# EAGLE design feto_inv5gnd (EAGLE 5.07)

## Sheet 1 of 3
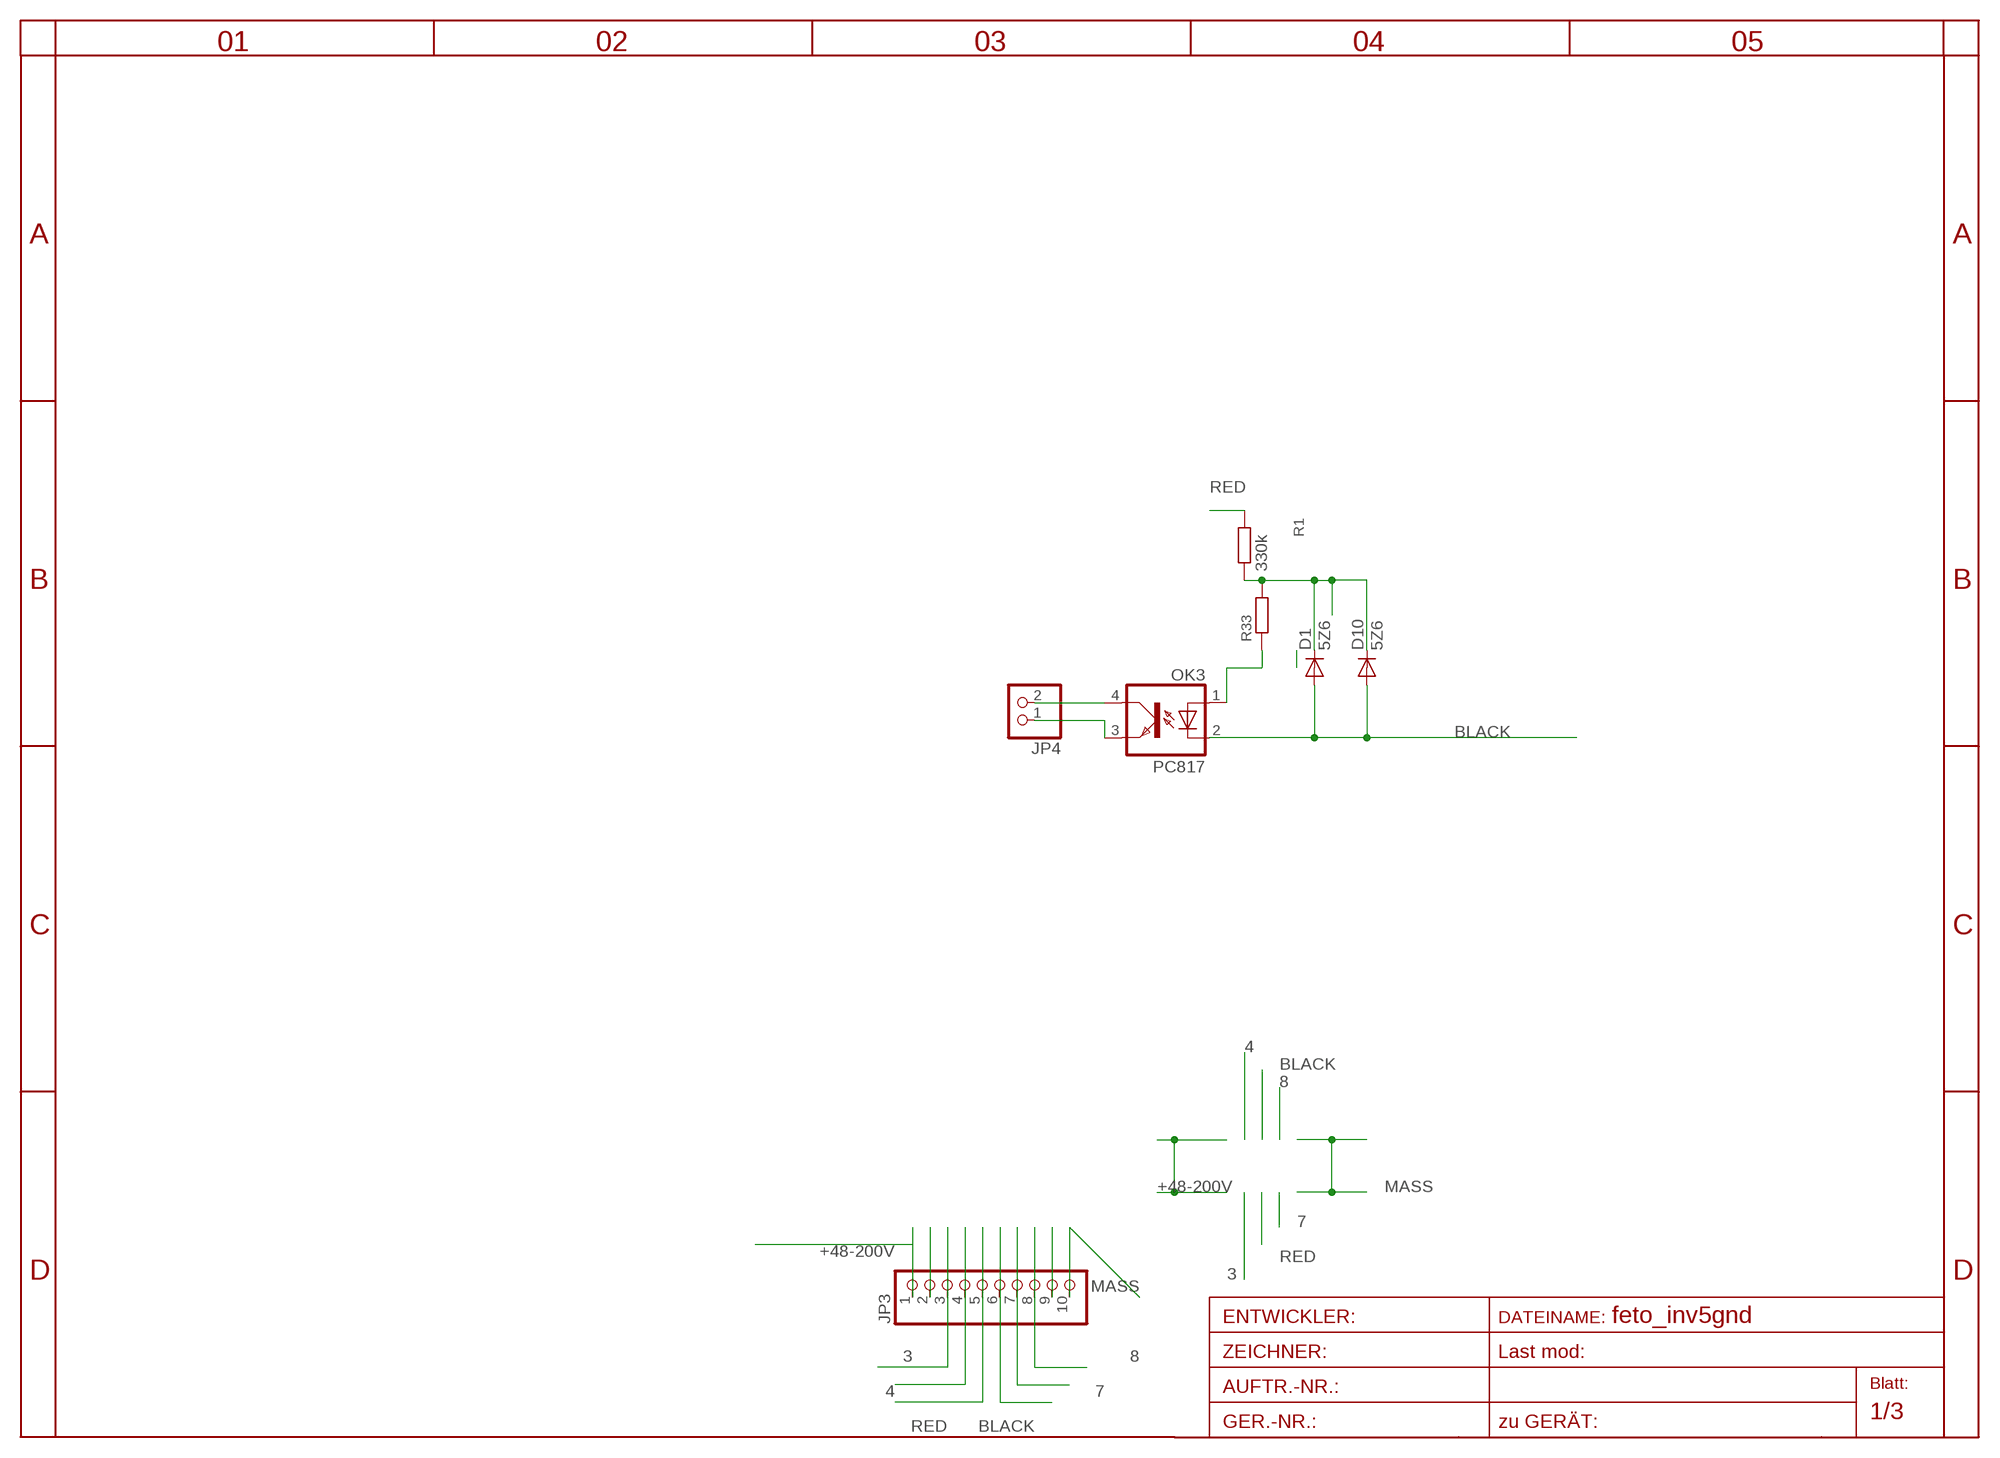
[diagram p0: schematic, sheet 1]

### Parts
D1  5Z6  DIODE-MINIMELF  [MINIMELF]
D10  5Z6  DIODE-MINIMELF  [MINIMELF]
JP3  PINHD-1X10  [1X10WIDE]
JP4  PINHD-1X2STR  [1X02]
OK3  PC817  [DIL04]
R1  330k  R-EU_0204/5  [0204/5]
R33  4k  R-EU_R0805  [R0805]

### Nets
3: JP3.3 ; also sheet 3
4: JP3.4 ; also sheet 3
7: JP3.7 ; also sheet 3
8: JP3.8 ; also sheet 3
+48-200V: JP3.1
BLACK: D1.A D10.A JP3.6 OK3.2(C) ; also sheet 3
MASS: JP3.10 ; also sheet 3
N$3: JP4.2 OK3.4(COL)
N$4: JP4.1 OK3.3(EMIT)
N$25: JP3.2
N$34: JP3.9
N$35: OK3.1(A) R33.1
N$36: D1.C D10.C R1.1 R33.2
RED: JP3.5 R1.2 ; also sheet 3

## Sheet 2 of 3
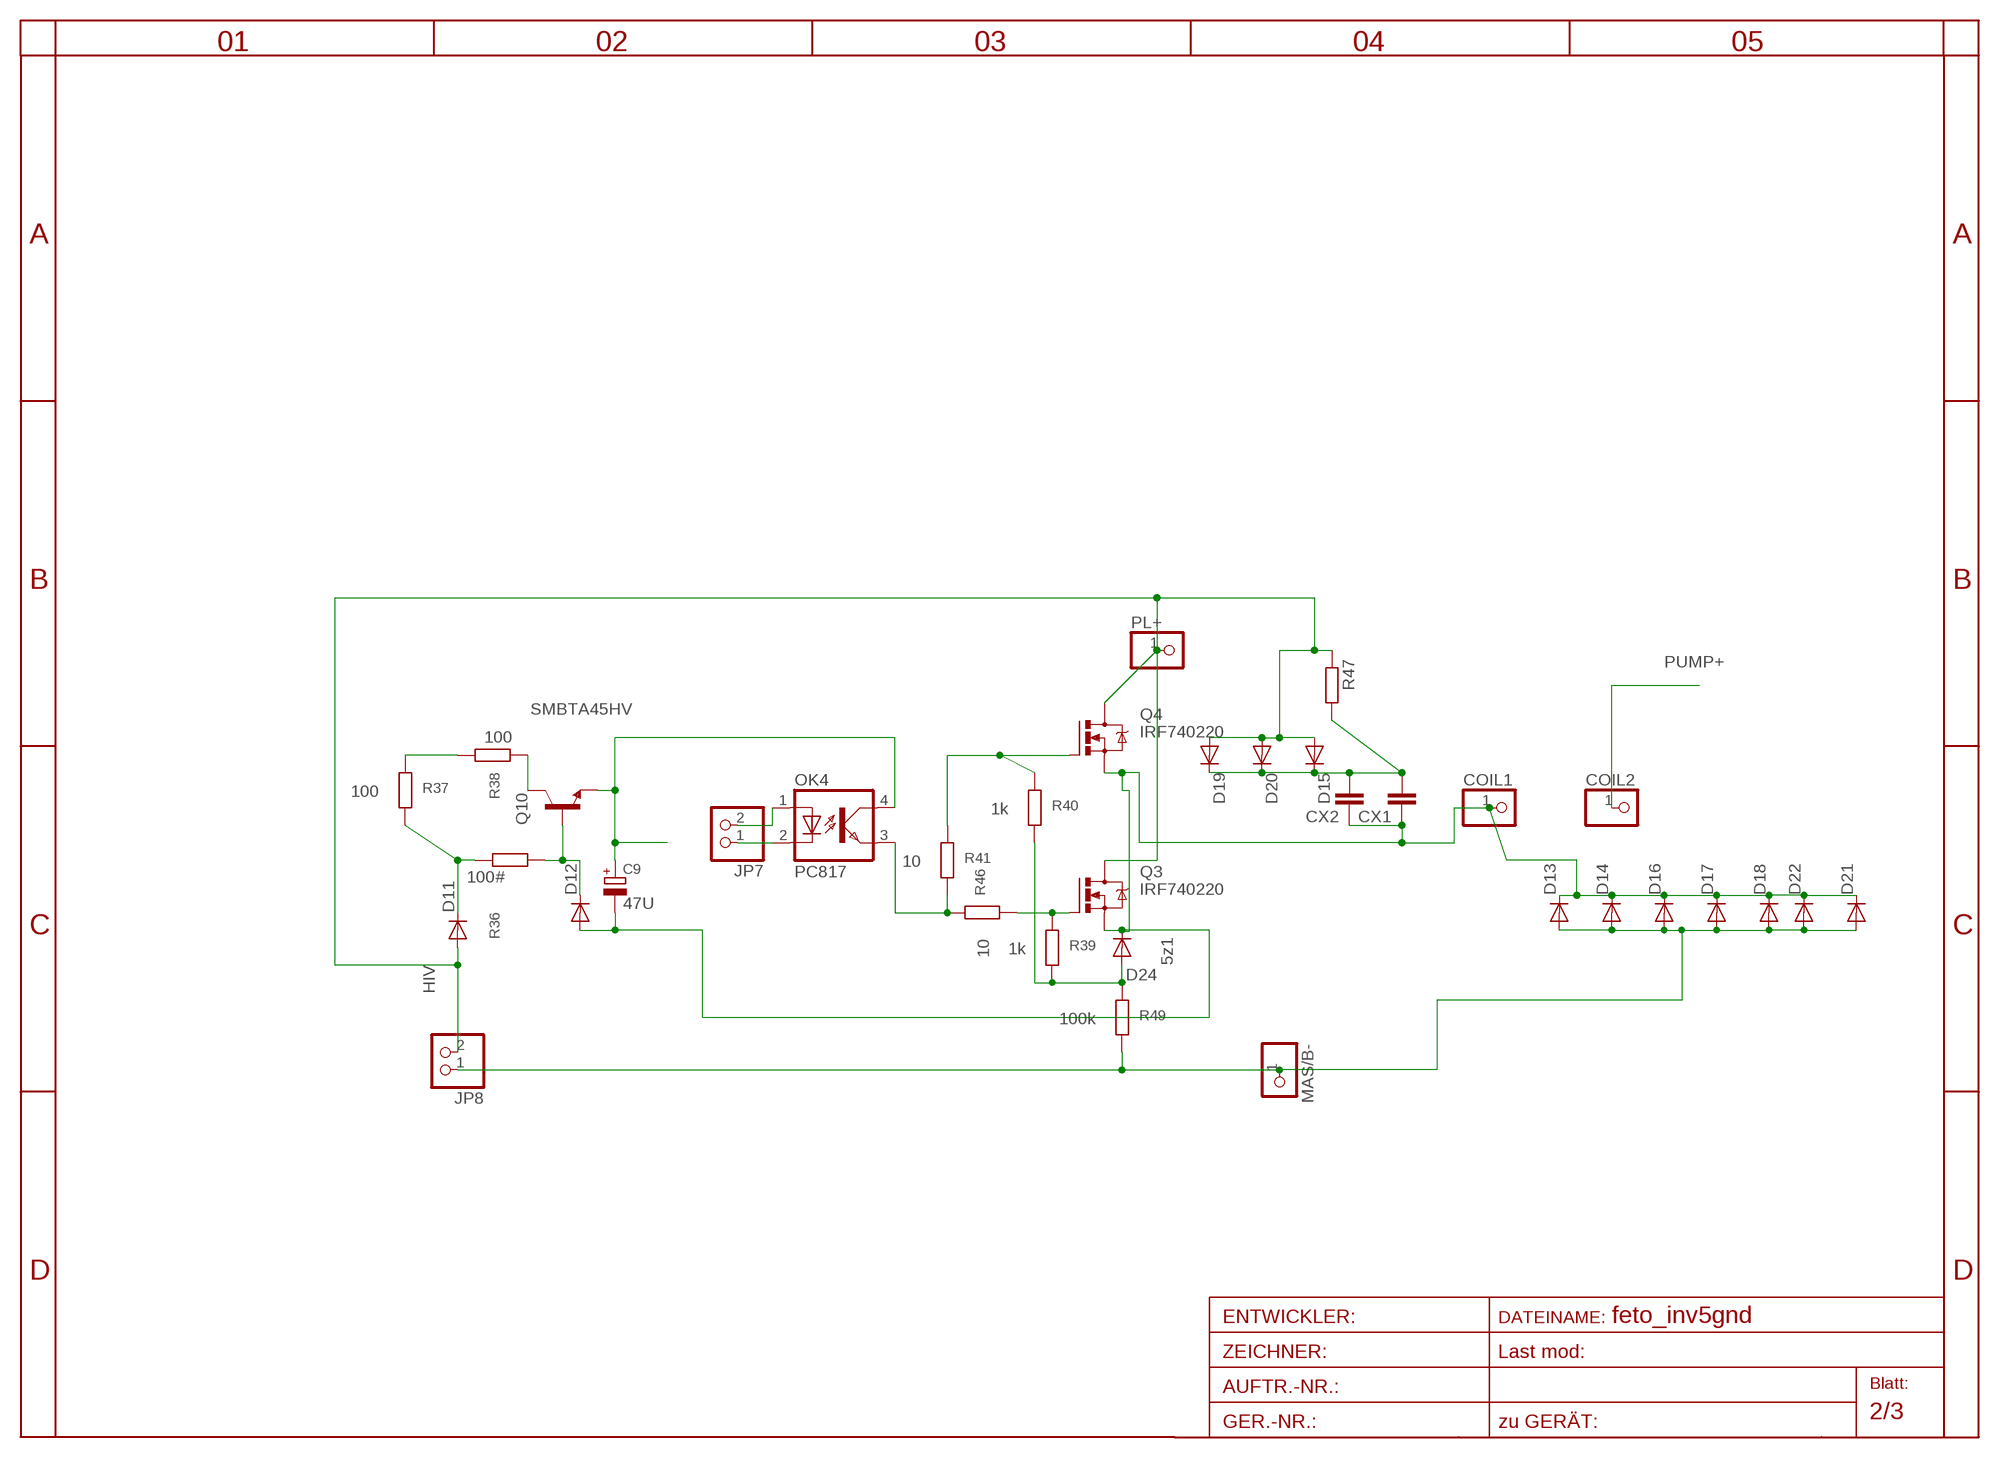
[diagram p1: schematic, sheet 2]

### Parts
C9  47U  CPOL-EUE2.5-6  [E2,5-6]
COIL1  PINHD-1X14.5MM  [1X4MM5]
COIL2  PINHD-1X14.5MM  [1X4MM5]
CX1  CXXC15B6  [XC15B6]
CX2  CXXC15B6  [XC15B6]
D11  DIODE-SMA-DO214  [SMA-DO214AC]
D12  DIODE-MINIMELF  [MINIMELF]
D13  DIODE-SMC  [SMC]
D14  DIODE-SMC  [SMC]
D15  DIODE-SMC  [SMC]
D16  DIODE-SMC  [SMC]
D17  DIODE-SMC  [SMC]
D18  DIODE-SMC  [SMC]
D19  DIODE-SMC  [SMC]
D20  DIODE-SMC  [SMC]
D21  DIODE-SMC  [SMC]
D22  DIODE-SMC  [SMC]
D24  5z1  DIODE-MINIMELF  [MINIMELF]
JP7  PINHD-1X2STR  [1X02]
JP8  PINHD-1X2STR  [1X02]
MAS/B-  PINHD-1X14.5MM  [1X4MM5]
OK4  PC817  [DIL04]
PL+  PINHD-1X14.5MM  [1X4MM5]
Q3  IRF740220  [TO220BV]
Q4  IRF740220  [TO220BV]
Q10  SMBTA45HV  [SOT23HV]
R36  100#  R-EU_R1206  [R1206]
R37  100  R-EU_R1206  [R1206]
R38  100  R-EU_R1206  [R1206]
R39  1k  R-EU_0207/30  [0207/30]
R40  1k  R-EU_0207/15  [0207/15]
R41  10  R-EU_0207/12  [0207/12]
R46  10  R-EU_0207/25  [0207/25]
R47  R-EU_CERAM35  [CERAM35]
R49  100k  R-EU_R1206  [R1206]

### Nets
B-: D13.A D14.A D16.A D17.A D18.A D21.A D22.A JP8.1 MAS/B-.1 R49.1
BATT-: D24.A R39.1 R40.1 R49.2
COIL1: C9.- COIL1.1 CX1.1 CX2.1 D12.A D13.C D14.C D16.C D17.C D18.C D21.C D22.C D24.C Q3.S Q4.S
HIV: D11.A D15.A D19.A D20.A JP8.2 PL+.1 Q3.D Q4.D R47.1
N$1: Q4.G R40.2 R41.2
N$42: JP7.1 OK4.2(C)
N$43: OK4.3(EMIT) R41.1 R46.2
N$44: JP7.2 OK4.1(A)
N$45: Q3.G R39.2 R46.1
N$48: C9.+ OK4.4(COL) Q10.2(E)
N$49: D11.K(C) R36.1 R37.1
N$50: R37.2 R38.1
N$51: D12.C Q10.1(B) R36.2
PUMP+: COIL2.1 ; also sheet 3
Q1: Q10.3(C) R38.2
SNUB: CX1.2 CX2.2 D15.C D19.C D20.C R47.2

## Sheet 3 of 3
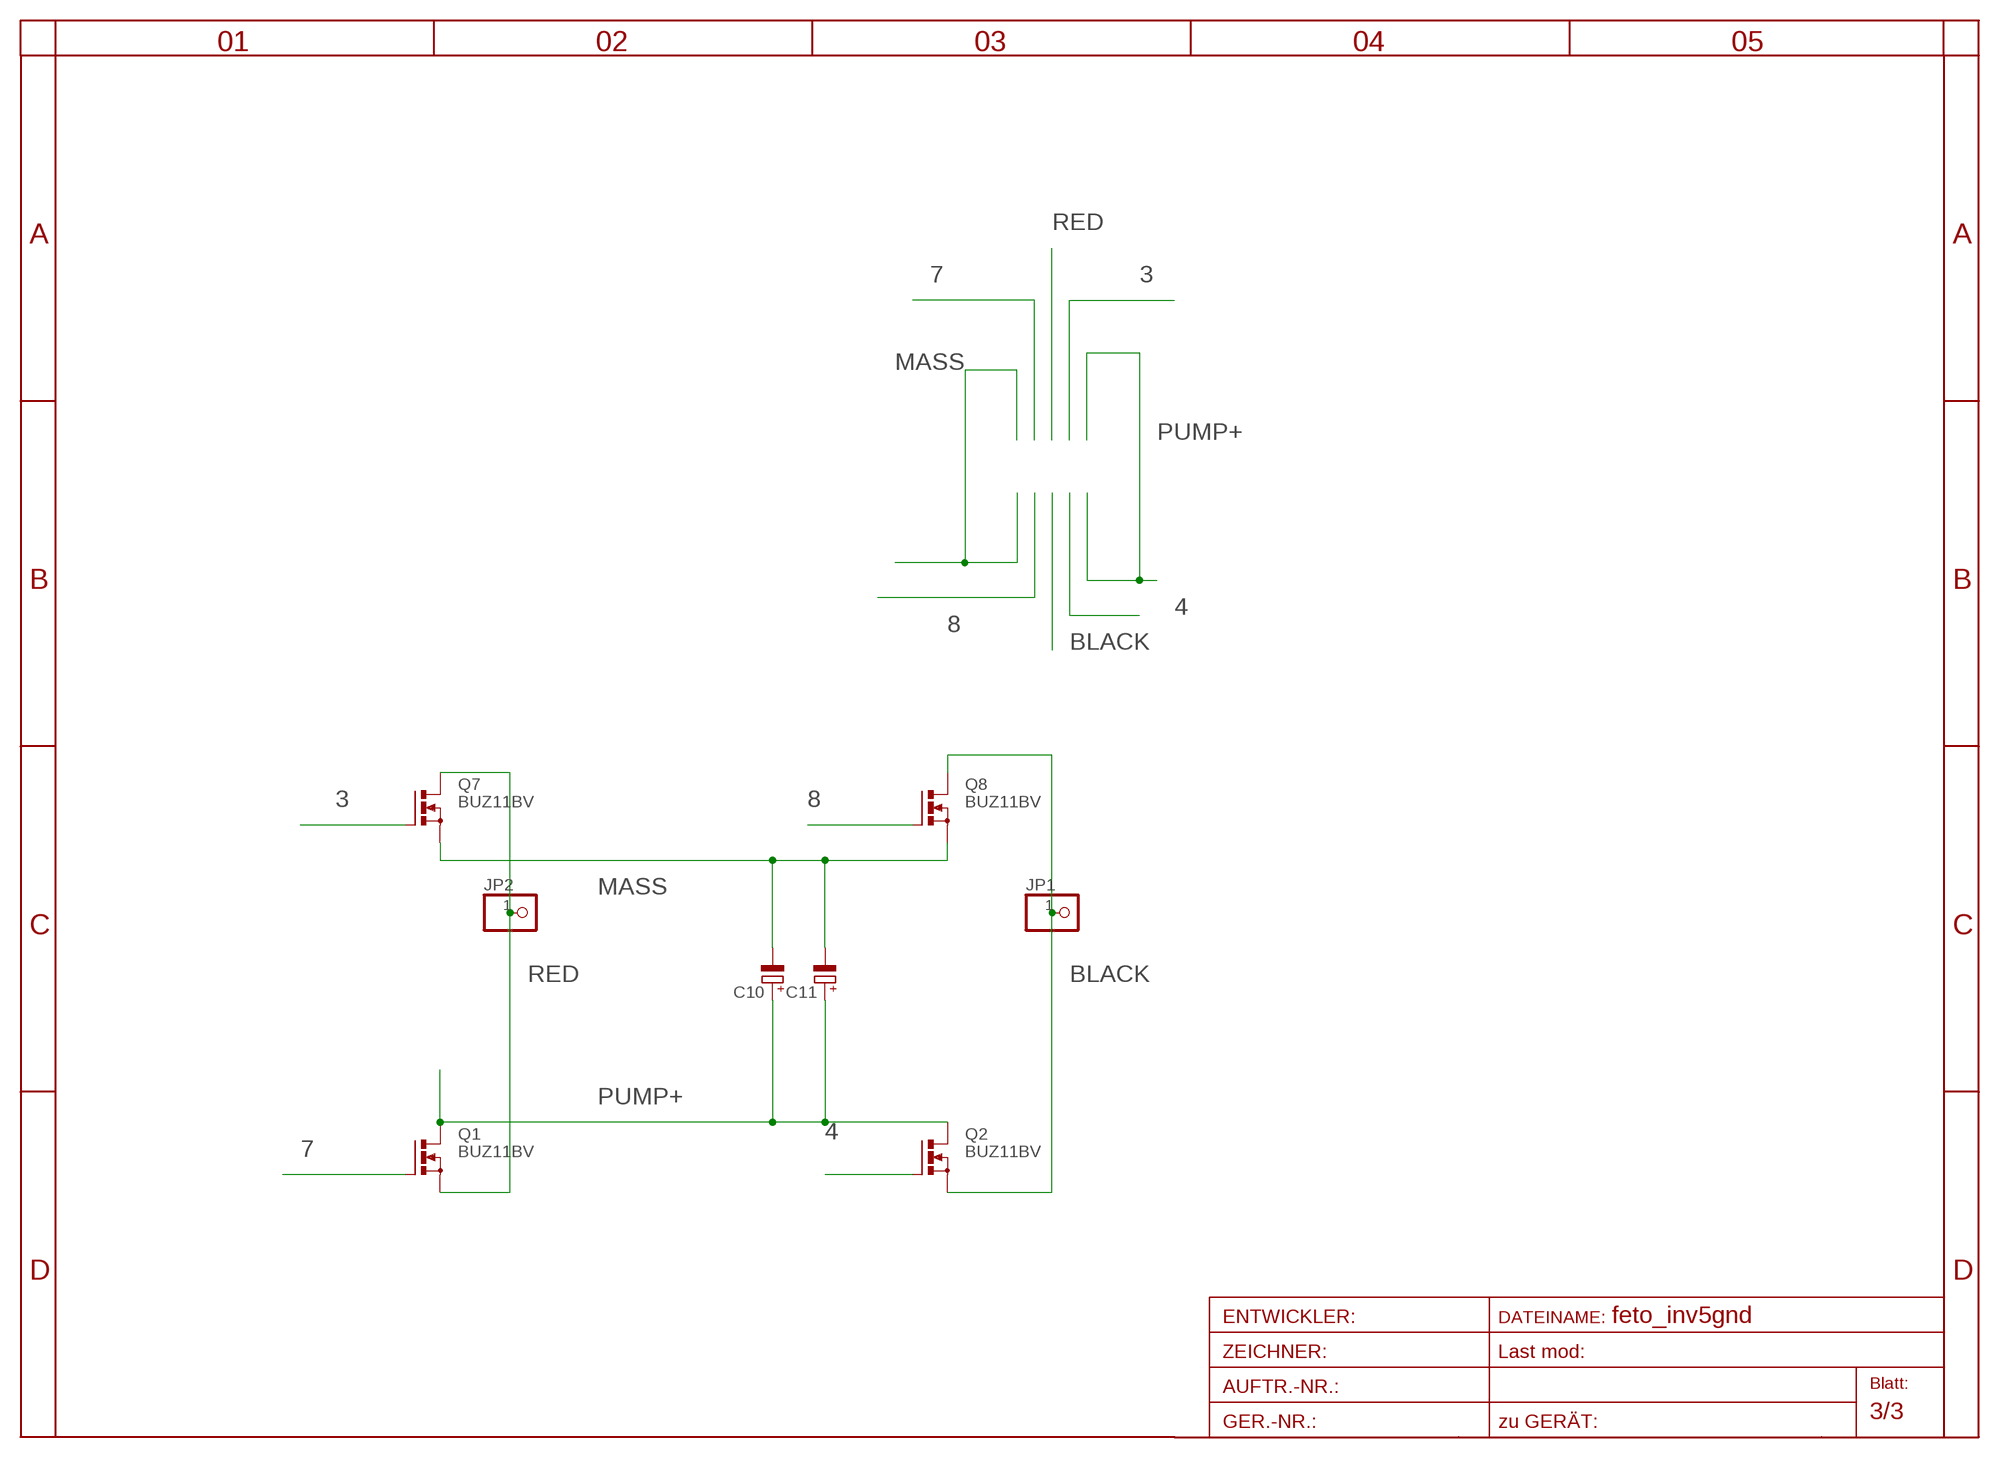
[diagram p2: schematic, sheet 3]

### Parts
C10  CPOL-EUE7.5-18  [E7,5-18]
C11  CPOL-EUE7.5-18  [E7,5-18]
JP1  PINHD-1X13MM2  [1X3MM2]
JP2  PINHD-1X13MM2  [1X3MM2]
Q1  BUZ11BV  [TO220BV]
Q2  BUZ11BV  [TO220BV]
Q7  BUZ11BV  [TO220BV]
Q8  BUZ11BV  [TO220BV]

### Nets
3: Q7.G ; also sheet 1
4: Q2.G ; also sheet 1
7: Q1.G ; also sheet 1
8: Q8.G ; also sheet 1
BLACK: JP1.1 Q2.S Q8.D ; also sheet 1
MASS: C10.- C11.- Q7.S Q8.S ; also sheet 1
PUMP+: C10.+ C11.+ Q1.D Q2.D ; also sheet 2
RED: JP2.1 Q1.S Q7.D ; also sheet 1

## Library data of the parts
C9 = rcl-2:CPOL-EU: POLARIZED CAPACITOR, European symbol
C10 C11 = rcl:CPOL-EU: POLARIZED CAPACITOR, European symbol
COIL1 COIL2 JP1 JP2 MAS/B- PL+ = pinhead:PINHD-1X1: PIN HEADER
CX1 CX2 = rcl:CX: X CAPACITOR
D1 D10-D22 D24 = diode:DIODE-: DIODE
JP3 = pinhead:PINHD-1X10: PIN HEADER
JP4 JP7 JP8 = pinhead:PINHD-1X2: PIN HEADER
OK3 OK4 = optocoupler:PC817: SHARP OPTO COUPLER
Q1 Q2 Q7 Q8 = transistor-power:BUZ11: N-CHANNEL MOS FET
Q3 Q4 = transistor-power:IRF740: N-CHANNEL MOS FET
Q10 = transistor-npn:SMBTA45
R1 R33 R36-R41 R46 R49 = rcl-2:R-EU_: RESISTOR, European symbol
R47 = rcl:R-EU_: RESISTOR, European symbol

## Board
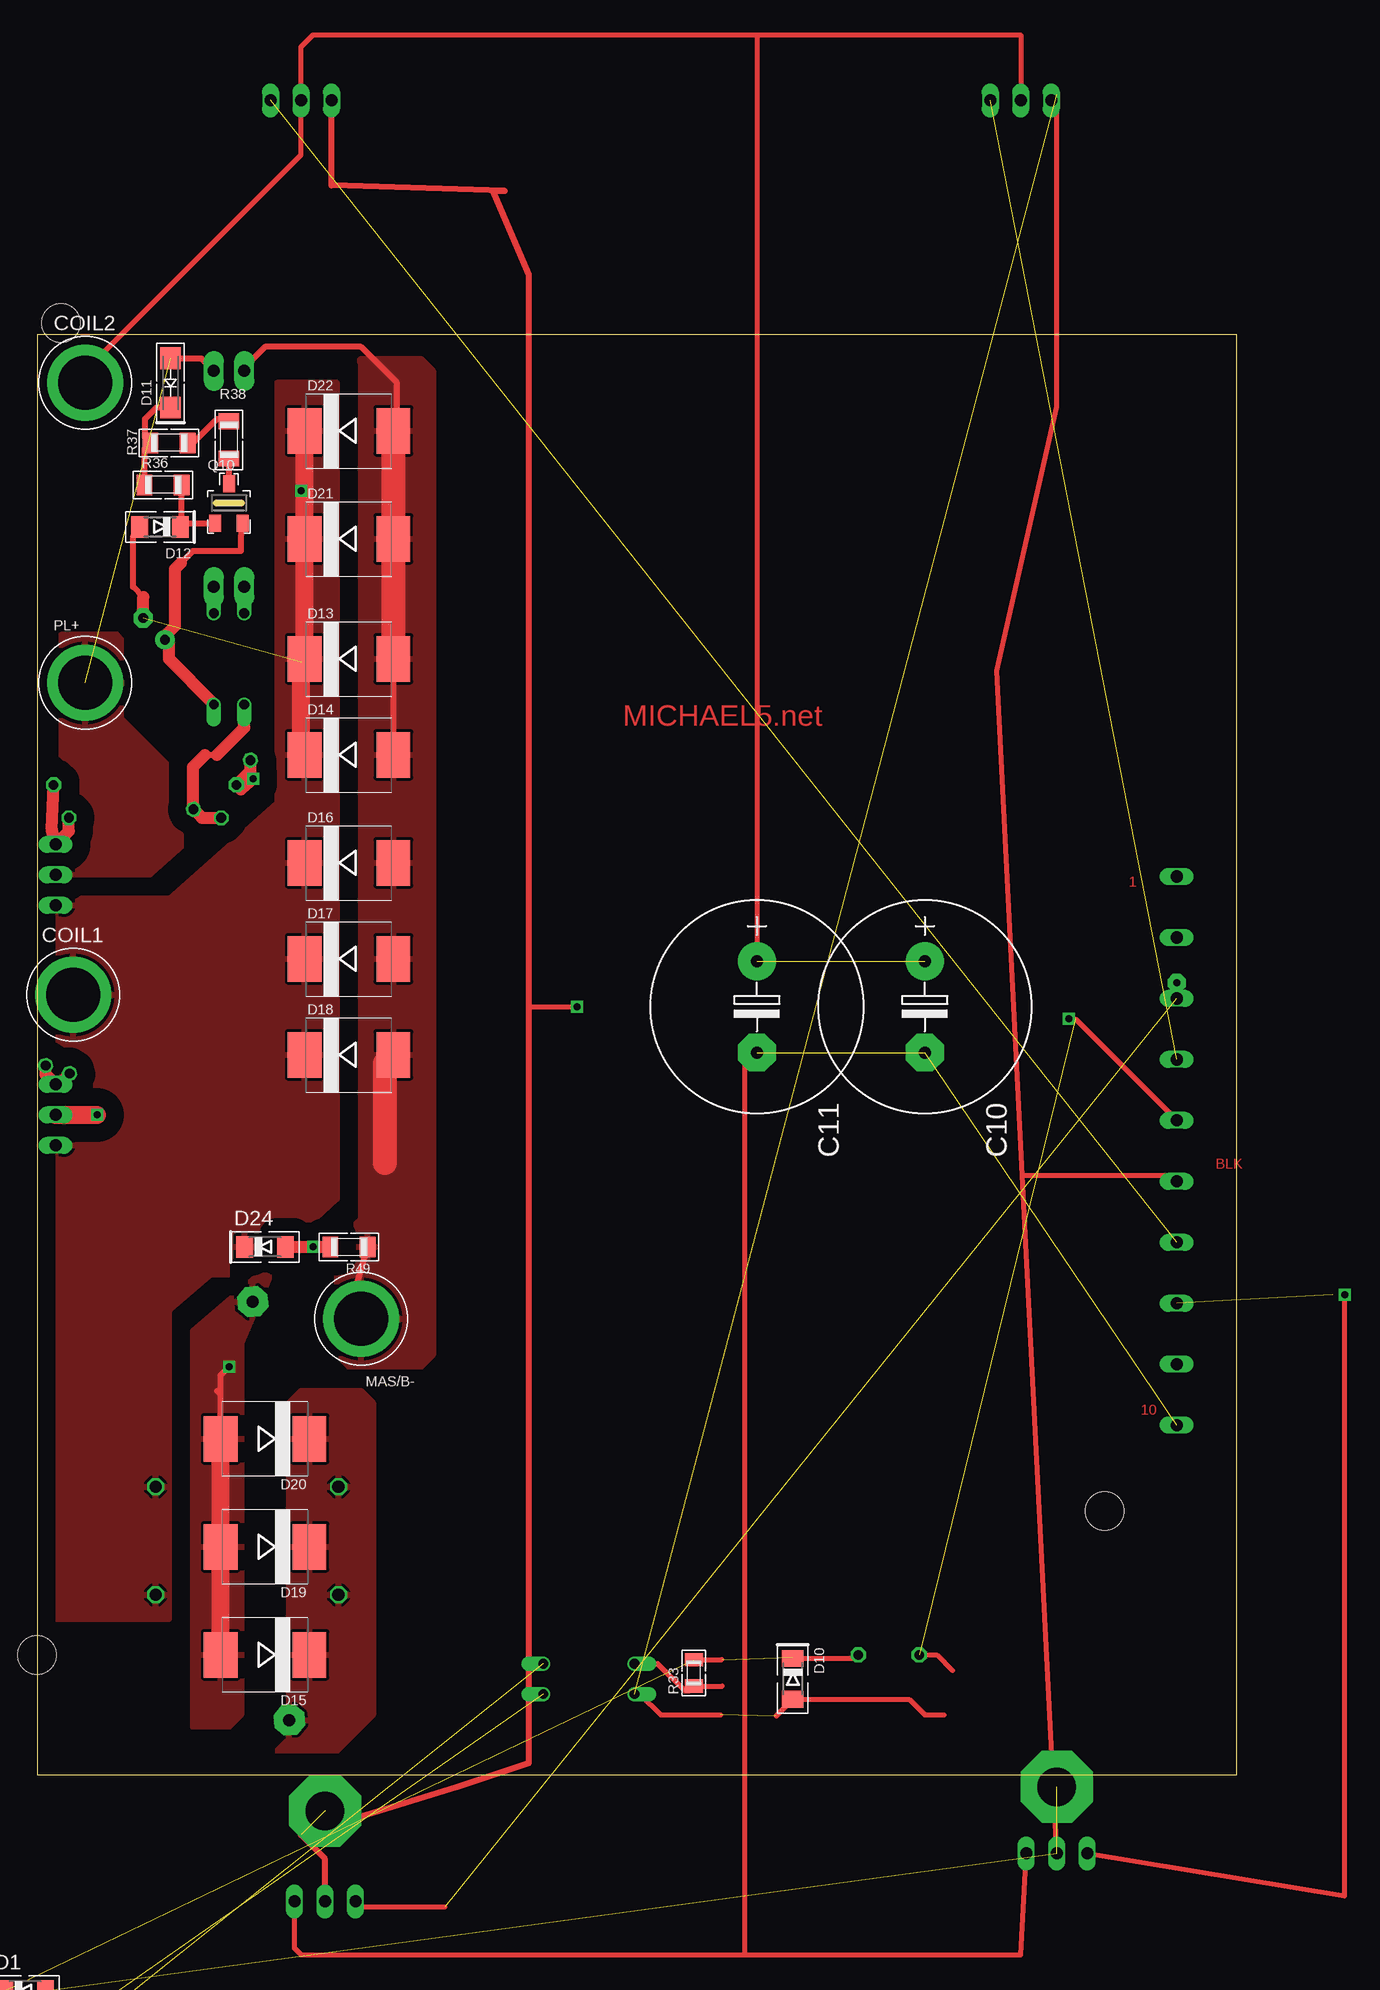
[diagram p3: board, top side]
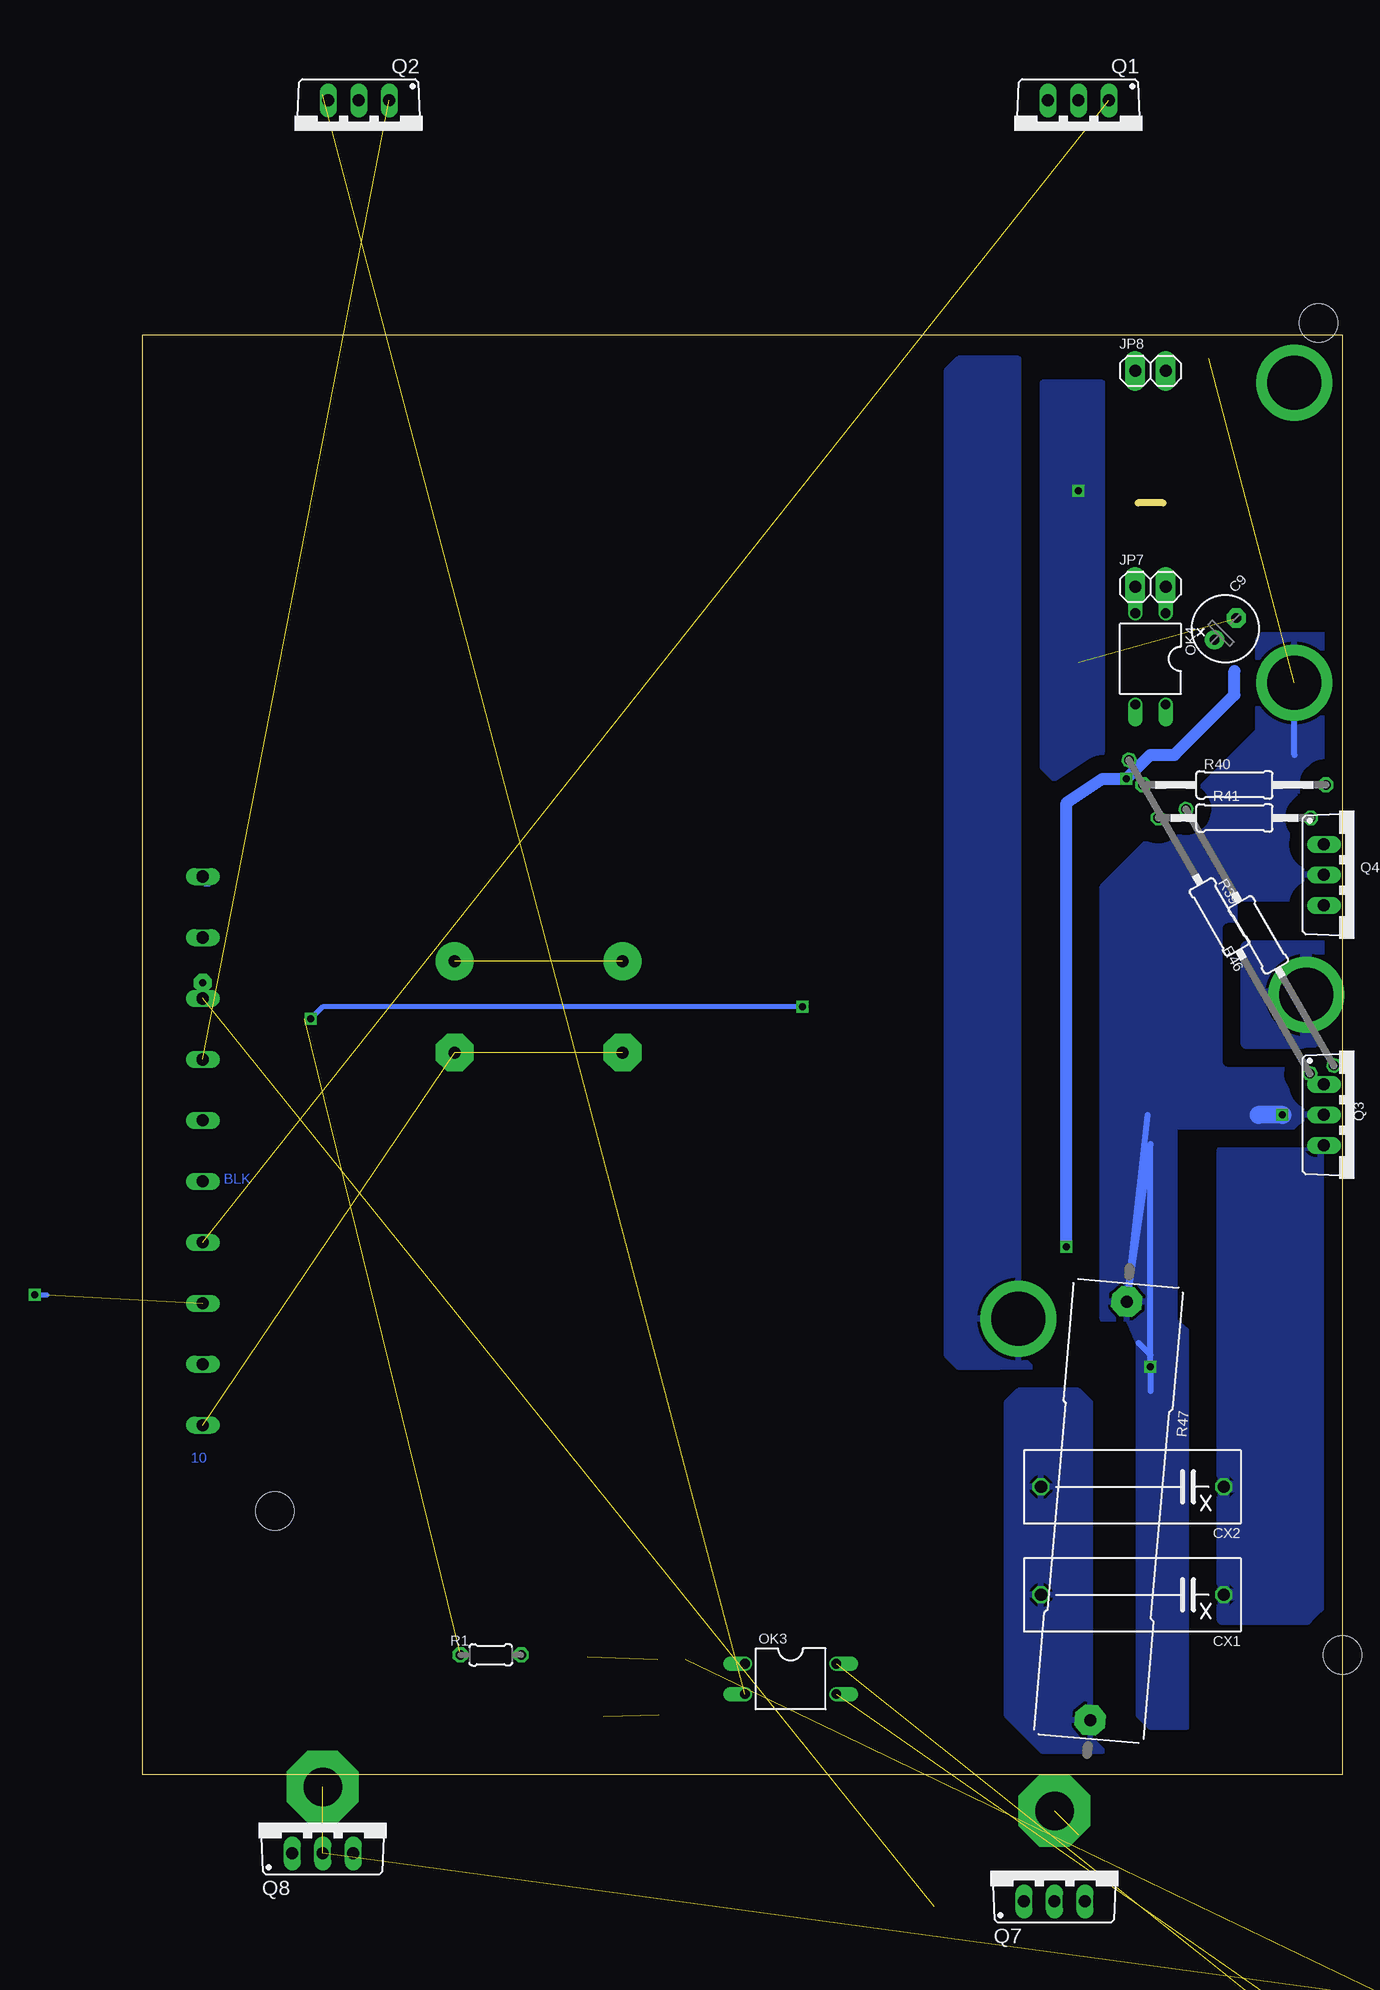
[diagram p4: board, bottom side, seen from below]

Size 100 x 120 mm. Coordinates in mm from the lower left corner, seen from the top.
Outline: 0,0 100,0 100,120 0,120 0,0
Copper layers (1*16): Top 0.035mm / dielectric 1.5mm / Bottom 0.035mm
Design rules "default *": minimum track width 12mil, minimum drill 24mil, track to track 8mil, track to pad 8mil, pad to pad 8mil, via to via 8mil, smd to smd 8mil, copper to edge 40mil, drill to drill 8mil, minimum pad ring 8mil, minimum via ring 8mil, stop-mask expansion 4mil, vias tented up to drill 0mil, thermal gap 10mil
Holes 3.2 mm at 2,121 0,10 120,132 89,22

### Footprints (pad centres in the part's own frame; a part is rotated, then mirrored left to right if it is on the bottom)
E2,5-6 = drill 0.813 pad 1.6 round: + -1.27,0 | drill 0.813 pad 1.6 octagon: - 1.27,0
E7,5-18 = drill 1.016 pad 3.15 round: + -3.81,0 | drill 1.016 pad 3.15 octagon: - 3.81,0
1X4MM5 = drill 4.5 pad 6.35 round: 1 0,0
XC15B6 = drill 1.016 octagon: 1 -7.62,0; 2 7.62,0
MINIMELF = smd 1.4 x 1.8: A 1.7,0; C -1.7,0
SMA-DO214AC = smd 1.8 x 1.7: A 2.05,-0.127; K -2.05,-0.127
SMC = smd 2.8 x 3.8: A 3.7,0; C -3.7,0
1X3MM2 = drill 3.2 pad 6 octagon: 1 0,0
1X10WIDE = drill 1.016 long: 1 -22.86,0; 2 -17.78,0; 3 -12.7,0; 4 -7.62,0; 5 -2.54,0; 6 2.54,0; 7 7.62,0; 8 12.7,0; 9 17.78,0; 10 22.86,0
1X02 = drill 1.016 pad 1.676 long: 1 -1.27,0; 2 1.27,0
DIL04 = drill 0.813 offset: 1 -1.27,-3.81; 2 1.27,-3.81; 3 1.27,3.81; 4 -1.27,3.81
TO220BV = drill 1.016 long: D 0,-2.54; G -2.54,-2.54; S 2.54,-2.54
SOT23HV = smd 1 x 1.4: 1 -1.15,-1.7; 2 1.15,-1.7; 3 0,1.6
0204/5 = drill 0.8 pad 1.27 octagon: 1 -2.54,0; 2 2.54,0
R0805 = smd 1.1 x 1.5: 1 -1.1,0; 2 1.1,0
R1206 = smd 1.3 x 1.7: 1 -1.55,0; 2 1.55,0
0207/30 = drill 0.813 octagon: 1 -15.08,0; 2 15.08,0
0207/15 = drill 0.8 pad 1.27 octagon: 1 -7.62,0; 2 7.62,0
0207/12 = drill 0.813 octagon: 1 -6.35,0; 2 6.35,0
0207/25 = drill 0.813 octagon: 1 -12.58,0; 2 12.08,0
CERAM35 = drill 1 pad 2.54 octagon: 1 -17.5,0; 2 17.5,0

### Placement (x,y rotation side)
C9  9.75,95.5 45 bottom
C10  74,64 270 top
C11  60,64 270 top
COIL1  3,65 0 top
COIL2  4,116 0 top
CX1  17.5,15 180 bottom
CX2  17.5,24 180 bottom
D1  not placed on the board
D10  63,8 270 top
D11  11,116 90 top
D12  10.25,104 180 top
D13  26,93 0 top
D14  26,85 0 top
D15  19,10 180 top
D16  26,76 0 top
D17  26,68 0 top
D18  26,60 0 top
D19  19,19 180 top
D20  19,28 180 top
D21  26,103 0 top
D22  26,112 0 top
D24  19,44 0 top
JP1  85,-1 0 top
JP2  24,-3 0 top
JP3  95,52 270 bottom
JP4  not placed on the board
JP7  16,99 0 bottom
JP8  16,117 0 bottom
MAS/B-  27,38 0 top
OK3  46,8 270 bottom
OK4  16,93 180 bottom
PL+  4,91 0 top
Q1  22,137 180 bottom  (outside the outline)
Q2  82,137 180 bottom  (outside the outline)
Q3  -1,55 270 bottom
Q4  -1,75 270 bottom
Q7  24,-8 0 bottom  (outside the outline)
Q8  85,-4 0 bottom  (outside the outline)
Q10  16,106 0 top
R1  71,10 180 bottom
R33  54.75,8.5 90 top
R36  10.5,107.5 0 top
R37  11,111 0 top
R38  16,111.25 270 top
R39  10.25,71.5 300 bottom
R40  9,82.5 0 bottom
R41  9,79.75 0 bottom
R46  7,70 120 bottom
R47  19.5,22 265 bottom
R49  26,44 180 top

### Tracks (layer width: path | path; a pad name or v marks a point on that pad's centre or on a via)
3  (via drill 0.6 pad 1.5)  (1 unrouted)
  Top 0.406: Q7.G 27,-11 34,-11
  Top 1: JP3.3 v95,66
4  (1 unrouted)
7  (1 unrouted)
8  (via drill 0.6)  (1 unrouted)
  Top 0.406: Q8.G 109,-10.08 v109,40
  Bottom 0.406: v109,40 108,40
B-
  Top 0.5: MAS/B-.1 25.55,37 R49.1 | D14.A D13.A | JP8.1 17.27,117.27 19,119 27,119 30,116 30,112.3 D22.A
  Top 2: D22.A D21.A D13.A | 29,51 29,59.3 D18.A
  pour Top (isolate 1.5, rank 3): 28,118 32,118 33,117 33,35 32,34 26,34 25,35 25,116 27,118
  pour Bottom (isolate 1.5, rank 3): 27,118 32,118 33,117 33,35 32,34 26,34 27,35
BATT-  (via drill 0.6)
  Top 0.5: 17,82.12 R40.1
  Top 1: R39.1 17.79,83.67 R40.1 | v18,83 17,82.12 | R49.2 v23,44 D24.A
  Bottom 1: v23,44 23,81 20,83 v18,83 16,85 14,85 9,90 9,92
BLACK  (4 unrouted)
  Top 0.406: Q8.D 82.13,49.96 | 82.13,49.96 80,92 85,114 85,140 Q2.S | JP3.6 94.5,49.96 82.13,49.96 | OK3.2 50.27,6.73 52,5 56.98,5 | 61.6,4.9 D10.A 72.7,6.3 74,5 75.61,5
COIL1  (via drill 0.6)  (1 unrouted)
  Top 0.5: 8.85,98.15 8,99 8,103.2 D12.A
  Top 1: C9.- 8.85,98.15
  Top 1.5: D22.C D21.C D13.C 22,92.7 22,84 22.3,84.3 D14.C
  other vias: 22,107
  pour Top (isolate 1.5, rank 2): 0,73 0,13 11,13 11,35 25,48 25,116 20,116 20,81 11,73
  pour Bottom (isolate 1.5): 20,116 25,116 25,84 24,83 21,83 20,84 20,93 20,94 20,113
  pour Bottom (isolate 1.5): 0,69 8,69 8,61 0,61
  pour Bottom (isolate 1.5, rank 3): 2,52 10,52 10,13 3,13 2,14 2,17
HIV  (via drill 0.6)  (1 unrouted)
  Top 0.5: D20.A 15.3,31.7 | 15.3,31.7 15,32 | 15.3,31.7 15.3,33.3 v16,34 | D11.A 13.68,118.05 JP8.2
  Top 1.5: D15.A D19.A D20.A | Q3.D v5,55
  Bottom 0.5: 16.23,55 R47.1 16,52.58 v16,34 | v16,34 16,32 | 4,85 PL+.1 | v16,34 16,35 17,36
  Bottom 1.5: v5,55 7,55
  pour Bottom (isolate 1.5, rank 2): 0,95 0,82 4,82 4,76 0,76 0,73 9,73 9,60 3,60 3,54 14,54 14,38 20,38 20,74 7,87 7,95
  pour Top (isolate 1.5): 13,37 20,43 17,36 17,5 16,4 13,4
  pour Bottom (isolate 1.5): 13,37 20,43 17,36 17,5 16,4 13,4
  pour Top (isolate 1.5, rank 4): 2,95 2,85 3,84 3,78 1,76 1,74 12,74 12,83 7,88 7,95
MASS  (2 unrouted)
  Top 0.406: Q7.S 21.46,-14.46 22,-15 59,-15 | 59,-15 82,-15 Q8.S | C11.- 59,59.19 59,-15
N$1
  Top 0.5: Q4.G 1.45,77.63
  Top 1: R40.2 1.23,78.79 Q4.G 2.65,78.65 R41.2
N$3  (1 unrouted)
N$4  (1 unrouted)
N$35
  Top 0.406: OK3.1 51.73,9.27 54,7 54.35,7 R33.1 57.12,7.4
N$36  (2 unrouted)
  Top 0.406: R33.2 57.08,9.6 | 62.91,9.79 D10.C 68.16,9.7 R1.1
N$42
  Top 1: OK4.2 JP7.1
N$43
  Top 0.5: 14,85 15,85 | R46.2 13,80.5
  Top 1: OK4.3 17.27,87.27 15,85 | 14,85 13,84 13,80.5 | R41.1 13.75,79.75 R46.2
N$44
  Top 1: OK4.1 JP7.2
N$45
  Top 1: R39.2 1.81,57.54 Q3.G 0.71,58.37 R46.1
N$48
  Top 0.5: OK4.4 14.73,89.27 | 11,94.25 C9.+ | Q10.2 17,103.15 17,102 13,102 12,101
  Top 1: 14.73,89.27 11,93 11,94.25 | C9.+ 10.65,94.9 11.5,95.75 11.5,100.5 12,101
N$49
  Top 0.5: R36.1 8.95,110.5 R37.1 9,111.45 9,113 9.95,113.95 D11.K
N$50
  Top 0.5: R37.2 13,111 15,113 15.8,113 R38.1
N$51
  Top 0.5: Q10.1 12.25,104.3 D12.C 12.05,104.1 R36.2
PUMP+  (1 unrouted)
  Top 0.406: COIL2.1 4,117 22,135 Q1.D 22,144 23,145 60,145 | 60,145 82,145 Q2.D | 60,145 C11.+
Q1
  Top 0.5: Q10.3 R38.2
RED  (via drill 0.6)  (2 unrouted)
  Top 0.406: JP3.5 86.54,63 v86,63 | 41,64 v45,64 | 76.31,8.69 75,10 R1.2
  Top 0.5: Q1.S 24.54,132.46 39,132 38,132 41,125 41,64 41,1 35,-1 22,-5 24,-7 Q7.D
  Bottom 0.406: v86,63 85,64 v45,64
SNUB
  pour Top (isolate 1.5, rank 2): 22,32 27,32 28,31 28,5 25,2 20,2 21,3 21,31
  pour Bottom (isolate 1.5, rank 2): 22,32 27,32 28,31 28,5 25,2 20,2 21,3 21,31

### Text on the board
Top: MICHAEL5.net | 1 | BLK | 10
Bottom: 1 | BLK | 10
